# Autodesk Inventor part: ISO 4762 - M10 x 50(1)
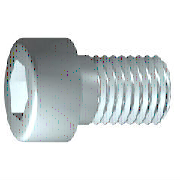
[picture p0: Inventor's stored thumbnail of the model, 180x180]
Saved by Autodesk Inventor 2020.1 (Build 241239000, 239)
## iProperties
Created: 2019-01
Part Number: ISO 4762 - M10 x 50(1)
Material: Edelstahl, 440C
Description: Innensechskantschraube
Document SubType Name: Modeling
Standard: ISO 4762
Designer: lutzd
Standard Revision: Fourth edition 2004-03-01
Standards Organization: ISO
Language: de-DE
Size Designation: M10 x 50
Categories: <MemberInstance><Categories><Category DisplayName="Verbindungselemente" InternalName="e4da775c-781d-43d5-af7c-5136215cf5a6" Mnemonic="FSTN"><Category DisplayNam
Mass: 43.2422 g
Surface Area: 25.8782 cm^2
Volume: 5.57964 cm^3
Density: 7.75 g/cm^3
Appearance: Semi-Polished(3)
IsCustomPart: 0
Author: lutzd
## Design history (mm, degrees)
body "Solid1"
sketch "Skizze1"
  geometry: L1 (-2.333, 0)-(50, 0); L2 (50, 0)-(50, 5); L3 (50, 5)-(18, 5); L4 (18, 5)-(17.08, 5); L5 (17.08, 5)-(0, 5); L6 (0, 5)-(0, 8); L7 (0, 8)-(-10, 8); L8 (-10, 8)-(-10, 4.619); L9 (-10, 4.619)-(-5, 4.619); L10 (-5, 4.619)-(-2.333, 0); L11 (-22, 0)-(62, 0) reference; L12 (0, -1.6)-(0, 9.6) reference; L13 (18, 5)-(0, 5)
  constraints: 22 end point, 6 parallel, 2 collinear, 2 perpendicular, 1 horizontal, 1 point on line
  dimensions: "d1" = 32 distance from line of L3.end L2 (= GEL); "d2" = 0.92028 distance of L4.end L3.end (computed from GAL); "d3" = 10 distance between parallel lines of L8 L6 (= KOH); "d4" = 5 distance of L8.end L9.end (= INTI); "d5" = 60 deg angle of L10 L1; "d6" = 10 diameter of L3 L1 (= GD); "d7" = 10 diameter of L5 L1 (= BDM); "d8" = 9.2376 diameter of L9 L1 (= 1.1547 x SW); "d9" = 16 diameter of L7 L1 (= KOD); "d26" = 50 distance between parallel lines of L12 L2 (= NLG)
workplane "Work Plane1"
fillet "Fillet2" dims "d30" = 0.1 (= R)
revolve "Körper" stored, may be unused: angle "d10" = 90 deg
sketch "Skizze2"
  geometry: L1 (0, -11.2)-(0, 11.2) reference; L2 (-11.2, 0)-(11.2, 0) reference; L3 (4.619, 0)-(2.309, -4); L4 (2.309, -4)-(-2.309, -4); L5 (-2.309, -4)-(-4.619, 0); L6 (-4.619, 0)-(-2.309, 4); L7 (-2.309, 4)-(2.309, 4); L8 (2.309, 4)-(4.619, 0); 2 further points
  constraints: 12 end point, 1 coincident, 1 horizontal alignment, 1 point on line, 12 other
extrude "Loch" join sketch "Skizze2" stored distance "d11" = 10; taper "d12" = 0 deg
fillet "Rundung1" dims "d17" = 1 (= RR)
feature "Gewinde" dims "d13" = 32 (= GEL), "d14" = 0
chamfer "Fase1" distance "d15" = 0.92018 (= -0.5 x SPD + 0.5 x GD); stored, may be unused: second distance "d16" = 0.92018 (= GUL), angle "d27" = 45 deg
other parameters: "GD" = 10 [user parameter; used in 2 equation terms], "NLG" = 50 [user parameter; used in 1 equation term], "GEL" = 32 [user parameter; used in 2 equation terms], "KOD" = 16 [user parameter; used in 1 equation term], "KOH" = 10 [user parameter; used in 1 equation term], "INTI" = 5 [user parameter; used in 1 equation term], "GAL" = 0.92018 (= 0.61345 x PTC) [user parameter; used in 1 equation term], "GUL" = 0.92018 (= 0.61345 x PTC) [user parameter; used in 1 equation term], "BDM" = 10 (= NND) [user parameter; used in 1 equation term], "SW" = 8 [user parameter; used in 2 equation terms], "RR" = 1 [user parameter; used in 1 equation term], "SPD" = 8.15965 (= NND - 1.2269 x PTC) [user parameter; used in 1 equation term], "d19" = 0, "d28" = 0, "d29" = 0, "R" = 0.1 [user parameter; used in 1 equation term], "TOA" = 30 deg [user parameter], "GD1" = 8.15965 (= THREADDIA - 1.2269 x PTC) [user parameter], "FAWI" = 45 deg [user parameter], "TPU" = 6.66667 (computed from PTC) [user parameter], "PTC" = 1.5 [user parameter; used in 5 equation terms], "E0" = 9.24 (= 1.155 x SW) [user parameter]
